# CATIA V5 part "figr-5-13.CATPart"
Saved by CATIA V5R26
Part number: Part1
Bounding box of the stored display mesh (mm): x 0 to 150, y -70 to 70, z -150 to 69.804
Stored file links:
  D:\_Deepak\CATIA\CATIA V5-6R2016_Deepak\Resources\Part files\Partfiles\c05_catia_v5_6r2016_prt\figr-5-13.CATPart
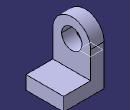
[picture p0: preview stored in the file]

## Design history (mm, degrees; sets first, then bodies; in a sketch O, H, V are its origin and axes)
Set1
  Plane1: type Normal, Curve edge [face of Pad1 | face of Pad1], RefPoint vertex of Pad2
Body1 (main body)
  Sketch1 on yz-plane, origin (0, 0, 0), H (0, 1, 0), V (0, 0, 1)
    arc A1 centre (0, 0) radius 70 from (70, 0) to (-70, 0) ccw
    point P1 (70, 0)
    point P2 (-70, 0)
    line L1 (-70, 0) -> (-70, -150)
    line L2 (-70, -150) -> (70, -150)
    line L3 (70, -150) -> (70, 0)
    circle A2 centre (0, 0) radius 37.5
    radius A1 = 70
    radius A2 = 37.5
    distance O L2 = 150
    coincidence: P1 H, P2 H
    tangency: L1 A1, L3 A1
    horizontal: L2 H
  Pad1: profile Sketch1, direction (1, 0, 0), length 50
  Sketch2 on face of Pad1, origin (50, 0, 0), H (0, 1, 0), V (0, 0, 1)
    line L1 (-70, -150) -> (70, -150)
    line L2 (70, -150) -> (70, -100)
    line L3 (70, -100) -> (-70, -100)
    line L4 (-70, -100) -> (-70, -150)
    reference projected line E1 (-70, -150) -> (70, -150) from edge [face of Pad1 | face of Pad1]
    reference projected line E2 (-70, 0) -> (-70, -150) from edge [face of Pad1 | face of Pad1]
    reference projected line E3 (70, -150) -> (70, 0) from edge [face of Pad1 | face of Pad1]
    length L2 = 50
    horizontal: L1 H, L3 H
    vertical: L2 V, L4 V
    coincidence: L1 E1, E2 L4, L2 E3
  Pad2: profile Sketch2, direction (1, 0, 0), length 100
